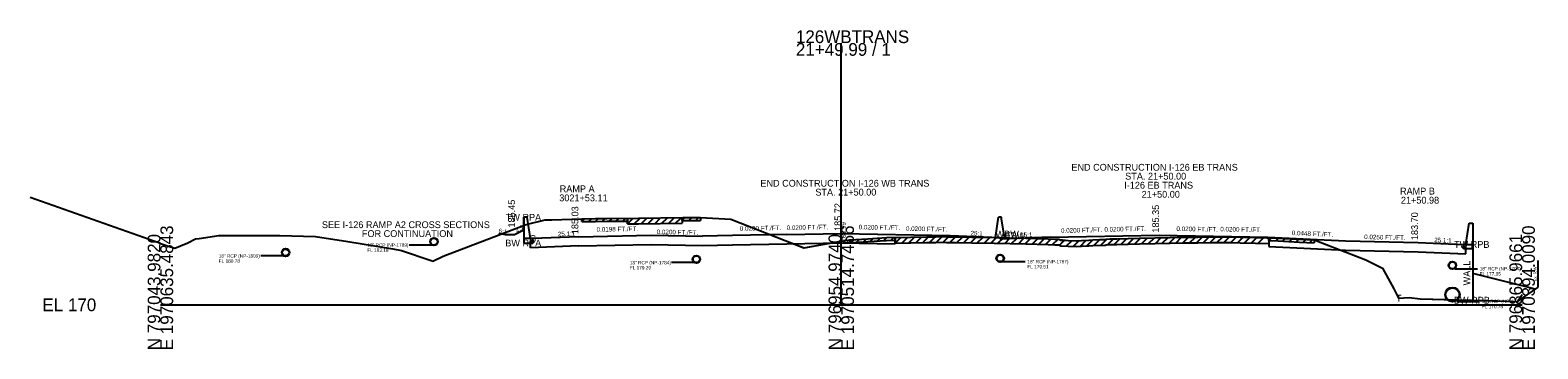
# Model space of a CAD drawing. Extents: x -6494 to 1970605, y -10 to 798140.
# Drawn here: x 971.3 to 1303.5, y 3990.3 to 4060.5 of the extents above; entities that cross this region are included whole.
import ezdxf

# ---------------------------------------------------------------- set-up
doc = ezdxf.new("R2010")
doc.units = 0
for name, color, linetype in [('RD_EX_SU_Misc_TxCode', 7, 'Continuous'), ('RD_GPK_XS_Cell', 7, 'Continuous'), ('RD_Sketch1', 7, 'Continuous'), ('RD_XS_Base', 7, 'Continuous'), ('RD_XS_Box', 7, 'Continuous'), ('RD_XS_EwShp', 7, 'Continuous'), ('RD_XS_ExGround', 7, 'Continuous'), ('RD_XS_ExPaveRet', 7, 'Continuous'), ('RD_XS_ExRW', 7, 'Continuous'), ('RD_XS_MedBWall', 7, 'Continuous'), ('RD_XS_Misc_Line', 7, 'Continuous'), ('RD_XS_Pave', 7, 'Continuous'), ('RD_XS_PaveOvlay', 7, 'Continuous'), ('RD_XS_PaveShd', 7, 'Continuous'), ('RD_XS_Pipe', 7, 'Continuous'), ('RD_XS_TieSlope', 7, 'Continuous'), ('RD_XS_TX_Elev_EX', 7, 'Continuous'), ('RD_XS_TX_Elev_PR', 7, 'Continuous'), ('RD_XS_TX_Misc', 7, 'Continuous'), ('RD_XS_TX_MkPT', 7, 'Continuous'), ('RD_XS_TX_Notes', 7, 'Continuous'), ('RD_XS_TX_Profile', 7, 'Continuous'), ('RD_XS_TX_Slope', 7, 'Continuous'), ('RD_XS_TX_Station', 7, 'Continuous')]:
    doc.layers.add(name, color=color, linetype=linetype)

msp = doc.modelspace()

# ---------------------------------------------------------------- linework, layer by layer
at = {"layer": 'RD_GPK_XS_Cell'}
for p, q in [((1150, 4000), (1150, 4057.66)), ((1000, 4000), (1150, 4000)), ((1150, 4000), (1300, 4000))]:
    msp.add_line(p, q, dxfattribs=at)
at = {"layer": 'RD_XS_Base'}
for p, q in [((1081.54, 4014.03), (1082.04, 4014.05)), ((1081.54, 4012.55), (1081.54, 4014.03)), ((1092.08, 4012.97), (1081.54, 4012.55)), ((1082.04, 4014.05), (1082.04, 4014.61)), ((1092.08, 4012.97), (1108.14, 4013.29)), ((1108.14, 4013.29), (1119.42, 4013.06)), ((1119.42, 4013.06), (1126, 4013.2)), ((1126, 4013.2), (1138, 4013.44)), ((1138, 4013.44), (1150, 4013.68)), ((1150, 4013.68), (1161.86, 4013.44)), ((1244.19, 4012.82), (1261.06, 4012.06)), ((1287.1, 4012.74), (1287.1, 4013.3)), ((1287.6, 4012.72), (1287.1, 4012.74)), ((1287.6, 4011.24), (1287.6, 4012.72)), ((1261.06, 4012.06), (1277.06, 4011.66)), ((1277.06, 4011.66), (1287.6, 4011.24))]:
    msp.add_line(p, q, dxfattribs=at)
at = {"layer": 'RD_XS_Box'}
for p, q in [((1080.04, 4016.45), (1080.04, 4014.61)), ((1082.04, 4014.61), (1080.04, 4014.61)), ((1287.1, 4013.3), (1289.11, 4013.3)), ((1289.11, 4013.3), (1289.11, 4001.02))]:
    msp.add_line(p, q, dxfattribs=at)
at = {"layer": 'RD_XS_ExGround'}
msp.add_line((1000, 4013.53), (971.31, 4023.67), dxfattribs=at)
for points in [[(1000, 4013.53), (1001.76, 4012.91), (1003.16, 4012.47), (1006.03, 4013.65), (1007.76, 4014.52), (1008.57, 4014.63), (1012.9, 4015.24), (1020.05, 4015.27), (1024.1, 4015.31), (1026.3, 4015.25), (1034.14, 4015.07), (1041.27, 4013.92), (1051.23, 4012.34), (1053.12, 4011.99), (1059.63, 4009.77), (1060.03, 4009.62), (1062.28, 4010.74), (1080.6, 4017.7), (1084.75, 4018.69), (1086.24, 4018.73), (1092.82, 4018.95), (1095.89, 4018.99), (1098.35, 4019.02), (1105.35, 4019.08), (1115.08, 4019.21), (1117.01, 4019.22), (1118.95, 4019.22), (1125.67, 4018.86), (1137.63, 4014.17), (1141.8, 4012.55), (1150, 4013.99), (1151.86, 4014.32), (1155.84, 4014.54), (1159.94, 4014.8), (1165.3, 4014.9), (1168.78, 4014.95), (1170.85, 4015), (1172.09, 4015.02), (1173.19, 4015), (1175.2, 4014.96), (1178.78, 4014.9), (1183.7, 4014.83), (1190.67, 4014.67), (1195.58, 4014.57), (1197.02, 4014.5), (1198.14, 4014.36), (1199.99, 4014.17), (1201.82, 4014.08), (1202.92, 4014.14), (1204.53, 4014.28), (1205.4, 4014.31), (1208.37, 4014.47), (1209.24, 4014.51), (1210.72, 4014.57), (1215.72, 4014.69), (1222.44, 4014.84), (1225.48, 4014.89), (1228.54, 4014.93), (1231.87, 4014.96), (1234.04, 4015), (1235.76, 4014.95), (1237.87, 4014.91), (1241.27, 4014.83), (1246.22, 4014.72), (1250.95, 4014.46), (1254.19, 4014.29), (1265.55, 4009.89), (1269.26, 4008.08), (1271.73, 4003.5), (1272.77, 4001.46), (1275.09, 4001.59), (1277.53, 4001.32), (1293.37, 4000.91), (1294.52, 4000.88), (1299, 4000.72), (1300, 4002.27)], [(1000, 4013.53), (1001.76, 4012.91), (1003.16, 4012.47), (1006.03, 4013.65), (1007.76, 4014.52), (1008.57, 4014.63), (1012.9, 4015.24), (1020.05, 4015.27), (1024.1, 4015.31), (1026.3, 4015.25), (1034.14, 4015.07), (1041.27, 4013.92), (1051.23, 4012.34), (1053.12, 4011.99), (1059.63, 4009.77), (1060.03, 4009.62), (1062.28, 4010.74), (1080.6, 4017.7), (1084.75, 4018.69), (1086.24, 4018.73), (1092.82, 4018.95), (1095.89, 4018.99), (1098.35, 4019.02), (1105.35, 4019.08), (1115.08, 4019.21), (1117.01, 4019.22), (1118.95, 4019.22), (1125.64, 4018.88), (1137.63, 4014.17), (1141.76, 4012.54), (1150, 4013.99), (1151.86, 4014.32), (1155.84, 4014.54), (1159.94, 4014.8), (1165.3, 4014.9), (1168.78, 4014.95), (1170.85, 4015), (1172.09, 4015.02), (1173.19, 4015), (1175.2, 4014.96), (1178.78, 4014.9), (1183.7, 4014.83), (1190.67, 4014.67), (1195.58, 4014.57), (1197.02, 4014.5), (1197.94, 4014.44), (1198.37, 4014.26), (1199.99, 4014.17), (1201.82, 4014.08), (1202.92, 4014.14), (1204.53, 4014.28), (1205.4, 4014.31), (1208.12, 4014.37), (1208.37, 4014.47), (1209.24, 4014.51), (1210.72, 4014.57), (1215.72, 4014.69), (1222.44, 4014.84), (1225.48, 4014.89), (1228.54, 4014.93), (1231.87, 4014.96), (1234.04, 4015), (1235.76, 4014.95), (1237.87, 4014.91), (1241.27, 4014.83), (1246.22, 4014.72), (1250.95, 4014.46), (1254.19, 4014.29), (1265.55, 4009.89), (1269.26, 4008.08), (1271.73, 4003.5), (1272.77, 4001.46), (1275.09, 4001.59), (1277.53, 4001.32), (1277.53, 4001.32), (1294.52, 4000.88), (1299, 4000.72), (1300, 4002.27)], [(1299, 4000.72), (1303.46, 4003.79)]]:
    msp.add_lwpolyline(points, dxfattribs=at)
at = {"layer": 'RD_XS_ExPaveRet'}
for p, q in [((1102.88, 4017.81), (1102.88, 4019.06)), ((1102.88, 4019.06), (1102.88, 4018.44)), ((1114.93, 4019.21), (1114.93, 4017.96)), ((1114.93, 4018.58), (1114.93, 4019.21)), ((1118.95, 4019.22), (1118.95, 4018.59)), ((1092.82, 4018.33), (1092.82, 4018.95)), ((1092.82, 4018.33), (1095.89, 4018.36)), ((1095.89, 4018.36), (1098.35, 4018.4)), ((1098.35, 4018.4), (1102.88, 4018.44)), ((1102.88, 4017.81), (1105.35, 4017.83)), ((1105.35, 4017.83), (1114.93, 4017.96)), ((1114.93, 4018.58), (1115.08, 4018.58)), ((1115.08, 4018.58), (1117.01, 4018.6)), ((1117.01, 4018.6), (1118.95, 4018.59)), ((1151.86, 4013.69), (1151.86, 4014.32)), ((1151.86, 4013.69), (1155.84, 4013.92)), ((1155.84, 4013.92), (1159.94, 4014.18)), ((1159.94, 4014.18), (1161.86, 4014.21)), ((1161.86, 4013.59), (1161.86, 4014.84)), ((1161.86, 4014.84), (1161.86, 4014.21)), ((1161.86, 4013.59), (1165.3, 4013.65)), ((1165.3, 4013.65), (1168.78, 4013.7)), ((1168.78, 4013.7), (1170.85, 4013.75)), ((1170.85, 4013.75), (1172.09, 4013.77)), ((1172.09, 4013.77), (1173.19, 4013.75)), ((1173.19, 4013.75), (1175.2, 4013.71)), ((1175.2, 4013.71), (1178.78, 4013.65)), ((1178.78, 4013.65), (1183.7, 4013.58)), ((1183.7, 4013.58), (1190.67, 4013.42)), ((1190.67, 4013.42), (1195.58, 4013.32)), ((1195.58, 4013.32), (1197.02, 4013.25)), ((1197.02, 4013.25), (1197.94, 4013.19)), ((1197.94, 4013.19), (1198.37, 4013.01)), ((1198.37, 4013.01), (1199.99, 4012.92)), ((1199.99, 4012.92), (1201.82, 4012.83)), ((1201.82, 4012.83), (1202.92, 4012.89)), ((1202.92, 4012.89), (1204.53, 4013.03)), ((1204.53, 4013.03), (1205.4, 4013.06)), ((1205.4, 4013.06), (1208.12, 4013.12)), ((1208.12, 4013.12), (1208.37, 4013.22)), ((1208.37, 4013.22), (1209.24, 4013.26)), ((1209.24, 4013.26), (1210.72, 4013.32)), ((1210.72, 4013.32), (1215.72, 4013.44)), ((1215.72, 4013.44), (1222.44, 4013.59)), ((1222.44, 4013.59), (1225.48, 4013.64)), ((1225.48, 4013.64), (1228.54, 4013.68)), ((1228.54, 4013.68), (1231.87, 4013.71)), ((1231.87, 4013.71), (1234.04, 4013.75)), ((1234.04, 4013.75), (1235.76, 4013.7)), ((1235.76, 4013.7), (1237.87, 4013.66)), ((1237.87, 4013.66), (1241.27, 4013.58)), ((1241.27, 4013.58), (1244.19, 4013.51)), ((1244.19, 4014.76), (1244.19, 4013.51)), ((1244.19, 4014.14), (1244.19, 4014.76)), ((1244.19, 4014.14), (1246.22, 4014.09)), ((1246.22, 4014.09), (1250.95, 4013.83)), ((1250.95, 4013.83), (1254.19, 4013.67)), ((1254.19, 4014.29), (1254.19, 4013.67))]:
    msp.add_line(p, q, dxfattribs=at)
at = {"layer": 'RD_XS_ExRW'}
msp.add_line((1303.46, 4009.79), (1303.46, 4003.79), dxfattribs=at)
at = {"layer": 'RD_XS_MedBWall'}
for p, q in [((1080.04, 4016.45), (1080.04, 4019.28)), ((1080.79, 4019.28), (1080.04, 4019.28)), ((1080.04, 4019.28), (1080.04, 4013.61)), ((1081.54, 4014.61), (1080.79, 4019.28)), ((1184, 4014.82), (1184.67, 4019.3)), ((1185.33, 4019.3), (1184.67, 4019.3)), ((1185.33, 4018.93), (1185.33, 4019.3)), ((1186, 4014.45), (1185.33, 4018.93)), ((1287.6, 4013.3), (1288.35, 4017.97)), ((1288.35, 4017.97), (1289.1, 4017.97)), ((1289.1, 4017.97), (1289.1, 4012.3)), ((1080.04, 4013.61), (1082.04, 4013.61)), ((1082.04, 4014.61), (1081.54, 4014.61)), ((1082.04, 4013.61), (1082.04, 4014.61)), ((1287.1, 4012.3), (1287.1, 4013.3)), ((1287.1, 4013.3), (1287.6, 4013.3)), ((1289.1, 4012.3), (1287.1, 4012.3))]:
    msp.add_line(p, q, dxfattribs=at)
at = {"layer": 'RD_XS_Misc_Line'}
for p, q in [((1101.87, 4018.43), (1102.51, 4019.06)), ((1102.88, 4017.81), (1104.15, 4019.07)), ((1104.39, 4017.83), (1105.66, 4019.09)), ((1105.89, 4017.84), (1107.17, 4019.11)), ((1107.4, 4017.86), (1108.68, 4019.13)), ((1108.91, 4017.88), (1110.19, 4019.15)), ((1110.42, 4017.9), (1111.69, 4019.17)), ((1111.93, 4017.92), (1113.2, 4019.19)), ((1113.44, 4017.94), (1114.71, 4019.2)), ((1114.93, 4018.58), (1115.56, 4019.21)), ((1116.44, 4018.59), (1117.07, 4019.22)), ((1117.95, 4018.59), (1118.57, 4019.22)), ((1092.82, 4018.33), (1093.45, 4018.96)), ((1094.33, 4018.34), (1094.96, 4018.98)), ((1095.84, 4018.36), (1096.47, 4018.99)), ((1097.35, 4018.38), (1097.98, 4019.02)), ((1098.85, 4018.4), (1099.49, 4019.03)), ((1100.36, 4018.42), (1101, 4019.05)), ((1151.86, 4013.69), (1152.53, 4014.35)), ((1153.37, 4013.78), (1154.04, 4014.44)), ((1154.88, 4013.86), (1155.54, 4014.53)), ((1156.39, 4013.95), (1157.06, 4014.62)), ((1157.89, 4014.05), (1158.56, 4014.72)), ((1159.4, 4014.14), (1160.07, 4014.8)), ((1160.91, 4014.19), (1161.55, 4014.83)), ((1161.86, 4013.59), (1163.14, 4014.86)), ((1163.37, 4013.61), (1164.65, 4014.89)), ((1164.88, 4013.64), (1166.16, 4014.91)), ((1166.39, 4013.67), (1167.66, 4014.94)), ((1167.9, 4013.69), (1169.18, 4014.96)), ((1169.4, 4013.72), (1170.69, 4014.99)), ((1170.91, 4013.75), (1172.2, 4015.02)), ((1172.42, 4013.77), (1173.65, 4014.99)), ((1173.93, 4013.74), (1175.16, 4014.96)), ((1175.44, 4013.7), (1176.68, 4014.93)), ((1176.95, 4013.68), (1178.18, 4014.91)), ((1178.46, 4013.66), (1179.69, 4014.89)), ((1179.97, 4013.63), (1181.2, 4014.86)), ((1181.47, 4013.61), (1182.71, 4014.84)), ((1182.98, 4013.59), (1184.22, 4014.81)), ((1184.49, 4013.56), (1185.72, 4014.78)), ((1186, 4013.53), (1187.23, 4014.75)), ((1187.51, 4013.49), (1188.74, 4014.72)), ((1189.02, 4013.46), (1190.25, 4014.68)), ((1190.53, 4013.43), (1191.76, 4014.65)), ((1192.03, 4013.4), (1193.27, 4014.62)), ((1193.54, 4013.36), (1194.77, 4014.59)), ((1195.05, 4013.33), (1196.26, 4014.54)), ((1196.56, 4013.27), (1197.75, 4014.46)), ((1198.07, 4013.14), (1199.15, 4014.22)), ((1199.58, 4012.94), (1200.77, 4014.13)), ((1201.09, 4012.87), (1202.34, 4014.11)), ((1202.6, 4012.87), (1203.96, 4014.23)), ((1204.1, 4012.99), (1205.43, 4014.31)), ((1205.61, 4013.06), (1206.9, 4014.34)), ((1207.12, 4013.1), (1208.51, 4014.48)), ((1208.63, 4013.23), (1209.94, 4014.54)), ((1210.14, 4013.3), (1211.44, 4014.59)), ((1211.65, 4013.35), (1212.93, 4014.62)), ((1213.16, 4013.38), (1214.44, 4014.66)), ((1214.67, 4013.41), (1215.95, 4014.69)), ((1216.17, 4013.45), (1217.46, 4014.73)), ((1217.68, 4013.48), (1218.97, 4014.76)), ((1219.19, 4013.52), (1220.48, 4014.8)), ((1220.7, 4013.55), (1221.99, 4014.83)), ((1222.21, 4013.59), (1223.49, 4014.86)), ((1223.72, 4013.61), (1224.99, 4014.88)), ((1225.23, 4013.63), (1226.5, 4014.9)), ((1226.73, 4013.65), (1228.01, 4014.92)), ((1228.24, 4013.67), (1229.52, 4014.94)), ((1229.75, 4013.69), (1231.02, 4014.95)), ((1231.26, 4013.71), (1232.54, 4014.98)), ((1232.77, 4013.73), (1234.05, 4015)), ((1234.28, 4013.75), (1235.5, 4014.96)), ((1235.79, 4013.7), (1237.02, 4014.93)), ((1237.3, 4013.67), (1238.53, 4014.9)), ((1238.8, 4013.64), (1240.03, 4014.86)), ((1240.31, 4013.6), (1241.54, 4014.82)), ((1241.82, 4013.57), (1243.05, 4014.79)), ((1244.19, 4014.14), (1244.81, 4014.75)), ((1245.7, 4014.1), (1246.31, 4014.71)), ((1247.21, 4014.04), (1247.81, 4014.63)), ((1248.72, 4013.95), (1249.32, 4014.55)), ((1250.23, 4013.87), (1250.82, 4014.46)), ((1251.74, 4013.79), (1252.34, 4014.39)), ((1253.25, 4013.72), (1253.84, 4014.31))]:
    msp.add_line(p, q, dxfattribs=at)
at = {"layer": 'RD_XS_Pave'}
for p, q in [((1092.08, 4015.01), (1108.14, 4015.33)), ((1138, 4015.48), (1126, 4015.24)), ((1138, 4015.48), (1150, 4015.72)), ((1150, 4015.72), (1174, 4015.24)), ((1196, 4014.87), (1220, 4015.35)), ((1196, 4014.87), (1220, 4015.35)), ((1220, 4015.35), (1244, 4014.87)), ((1220, 4015.35), (1244, 4014.87)), ((1244, 4014.87), (1261.06, 4014.1)), ((1261.06, 4014.1), (1277.06, 4013.7))]:
    msp.add_line(p, q, dxfattribs=at)
at = {"layer": 'RD_XS_PaveOvlay'}
for p, q in [((1161.86, 4014.84), (1165.3, 4014.9)), ((1161.86, 4014.84), (1161.86, 4013.44)), ((1165.3, 4014.9), (1168.78, 4014.95)), ((1168.78, 4014.95), (1170.85, 4015)), ((1170.85, 4015), (1172.09, 4015.02)), ((1172.09, 4015.02), (1173.19, 4015)), ((1173.19, 4015), (1175.2, 4014.96)), ((1175.2, 4014.96), (1178.78, 4014.9)), ((1178.78, 4014.9), (1183.7, 4014.83)), ((1183.7, 4014.83), (1190.67, 4014.67)), ((1190.67, 4014.67), (1195.58, 4014.57)), ((1195.58, 4014.57), (1197.02, 4014.5)), ((1197.02, 4014.5), (1197.94, 4014.44)), ((1197.94, 4014.44), (1198.37, 4014.26)), ((1198.37, 4014.26), (1199.99, 4014.17)), ((1199.99, 4014.17), (1201.82, 4014.08)), ((1201.82, 4014.08), (1202.92, 4014.14)), ((1202.92, 4014.14), (1204.53, 4014.28)), ((1204.53, 4014.28), (1205.4, 4014.31)), ((1205.4, 4014.31), (1208.12, 4014.37)), ((1208.12, 4014.37), (1208.37, 4014.47)), ((1208.37, 4014.47), (1209.24, 4014.51)), ((1209.24, 4014.51), (1210.72, 4014.57)), ((1210.72, 4014.57), (1215.72, 4014.69)), ((1215.72, 4014.69), (1222.44, 4014.84)), ((1222.44, 4014.84), (1225.48, 4014.89)), ((1225.48, 4014.89), (1228.54, 4014.93)), ((1228.54, 4014.93), (1231.87, 4014.96)), ((1231.87, 4014.96), (1234.04, 4015)), ((1234.04, 4015), (1235.76, 4014.95)), ((1235.76, 4014.95), (1237.87, 4014.91)), ((1237.87, 4014.91), (1241.27, 4014.83)), ((1241.27, 4014.83), (1244.19, 4014.76)), ((1244.19, 4014.76), (1244.19, 4012.82))]:
    msp.add_line(p, q, dxfattribs=at)
at = {"layer": 'RD_XS_PaveShd'}
for p, q in [((1092.08, 4015.01), (1082.04, 4014.61)), ((1108.14, 4015.33), (1119.42, 4015.1)), ((1126, 4015.24), (1119.42, 4015.1)), ((1174, 4015.24), (1185, 4014.8)), ((1196, 4014.87), (1185, 4014.43)), ((1185, 4014.8), (1185, 4014.43)), ((1277.06, 4013.7), (1287.1, 4013.3))]:
    msp.add_line(p, q, dxfattribs=at)
at = {"layer": 'RD_XS_Pipe'}
for p, q in [((1059.77, 4013.18), (1054.77, 4013.18)), ((1027.09, 4010.78), (1022.09, 4010.78)), ((1117.59, 4009.29), (1112.59, 4009.29)), ((1185.5, 4009.51), (1190.5, 4009.51)), ((1285.14, 4007.95), (1290.14, 4007.95)), ((1285.64, 4000.75), (1290.64, 4000.75))]:
    msp.add_line(p, q, dxfattribs=at)
for centre, radius in [((1060.27, 4013.93), 0.85), ((1060.27, 4013.93), 0.75), ((1027.59, 4011.53), 0.85), ((1027.59, 4011.53), 0.75), ((1118.09, 4010.04), 0.85), ((1118.09, 4010.04), 0.75), ((1185, 4010.26), 0.85), ((1185, 4010.26), 0.75), ((1284.64, 4008.7), 0.85), ((1284.64, 4008.7), 0.75), ((1284.64, 4002.25), 1.6), ((1284.64, 4002.25), 1.5)]:
    msp.add_circle(centre, radius, dxfattribs=at)
at = {"layer": 'RD_XS_TieSlope'}
for p, q in [((1080.04, 4016.45), (1078.04, 4015.45)), ((1074.61, 4015.69), (1074.61, 4015.42)), ((1076.04, 4015.45), (1074.61, 4015.69)), ((1078.04, 4015.45), (1076.04, 4015.45)), ((1302.93, 4003.42), (1289.11, 4006.87))]:
    msp.add_line(p, q, dxfattribs=at)

# ---------------------------------------------------------------- texts
at = {"layer": 'RD_EX_SU_Misc_TxCode'}
msp.add_text('G', height=1.5, dxfattribs=at).set_placement((1081.29, 4013.86))
at = {"layer": 'RD_GPK_XS_Cell'}
for s, p in [('126WBTRANS', (1140, 4057.66)), ('21+49.99 / 1', (1140, 4054.86)), ('EL 170', (974, 3998.6))]:
    msp.add_text(s, height=2.8, dxfattribs=at).set_placement(p)
for s, p in [('E 1970635.4843', (1002.8, 3990)), ('E 1970514.7466', (1152.8, 3990)), ('E 1970394.0090', (1302.8, 3990)), ('N 797043.9820', (1000, 3990)), ('N 796954.9740', (1150, 3990)), ('N 796865.9661', (1300, 3990))]:
    msp.add_text(s, height=2.8, rotation=90, dxfattribs=at).set_placement(p)
at = {"layer": 'RD_Sketch1'}
msp.add_text('T', height=1.5, dxfattribs=at).set_placement((1272.21, 4000.71))
at = {"layer": 'RD_XS_EwShp'}
for s, p in [('TW RPA', (1076.08, 4018.53)), ('BW RPA', (1075.98, 4012.86)), ('TW RPB', (1285, 4012.55)), ('BW RPB', (1284.97, 4000.27))]:
    msp.add_text(s, height=1.5, dxfattribs=at).set_placement(p)
at = {"layer": 'RD_XS_ExRW'}
msp.add_text('Ex. R/W ', height=0.65, rotation=90, dxfattribs=at).set_placement((1303.21, 4005.17))
at = {"layer": 'RD_XS_Pipe'}
for s, p in [('18" RCP (NP-1789)', (1045.59, 4012.8)), ('FL 183.18', (1045.59, 4011.68)), ('18" RCP (NP-1809)', (1012.86, 4010.4)), ('FL 180.78', (1012.86, 4009.28)), ('18" RCP (NP-1784)', (1103.42, 4008.92)), ('18" RCP (NP-1787)', (1191, 4009.14)), ('FL 179.29', (1103.42, 4007.79)), ('FL 179.51', (1191, 4008.01)), ('18" RCP (NP-1794)', (1290.64, 4007.57)), ('FL 177.95', (1290.64, 4006.45)), ('36" RCP (NP-1773)', (1291.14, 4000.38)), ('FL 170.75', (1291.14, 3999.25))]:
    msp.add_text(s, height=0.75, dxfattribs=at).set_placement(p)
at = {"layer": 'RD_XS_TX_Elev_EX'}
msp.add_text('183.99', height=1, rotation=90, dxfattribs=at).set_placement((1151, 4013.99))
at = {"layer": 'RD_XS_TX_Elev_PR'}
for s, p in [(' 185.03', (1092.08, 4015.01)), (' 185.72', (1150, 4015.72)), (' 185.35', (1220, 4015.35)), (' 183.70', (1277.06, 4013.7))]:
    msp.add_text(s, height=1.5, rotation=90, dxfattribs=at).set_placement(p)
at = {"layer": 'RD_XS_TX_Misc'}
msp.add_text('185.45', height=1.5, rotation=90, dxfattribs=at).set_placement((1078.12, 4017.02))
at = {"layer": 'RD_XS_TX_MkPT'}
for s, p in [('WBW', (1184, 4014.82)), ('EBW', (1186, 4014.45))]:
    msp.add_text(s, height=1.5, dxfattribs=at).set_placement(p)
at = {"layer": 'RD_XS_TX_Notes'}
for s, p in [('END CONSTRUCTION I-126 EB TRANS', (1200.69, 4029.55)), ('STA. 21+50.00', (1212.55, 4027.59)), ('END CONSTRUCTION I-126 WB TRANS', (1132.18, 4026.03)), ('STA. 21+50.00', (1144.29, 4024.07)), ('SEE I-126 RAMP A2 CROSS SECTIONS', (1035.58, 4016.9)), ('FOR CONTINUATION', (1044.39, 4014.94))]:
    msp.add_text(s, height=1.5, dxfattribs=at).set_placement(p)
msp.add_text('WALL', height=1.5, rotation=90, dxfattribs=at).set_placement((1288.55, 4004.29))
at = {"layer": 'RD_XS_TX_Profile'}
for s, rotation, p in [('25:1', 357.7094, (1178.46, 4015.31)), ('25:1', 2.2906, (1189.44, 4014.86)), ('25.1:1', 357.7181, (1280.61, 4013.81))]:
    msp.add_text(s, height=1, rotation=rotation, dxfattribs=at).set_placement(p)
at = {"layer": 'RD_XS_TX_Slope'}
for s, rotation, p in [('6:1', 350.5377, (1074.42, 4015.86)), ('2:1', 26.5651, (1078.44, 4015.96)), ('25.1:1', 2.2825, (1087.58, 4015.08)), ('0.0198 FT./FT.', 1.1347, (1096.1, 4016.09)), ('0.0200 FT./FT.', 358.8542, (1109.32, 4015.6)), ('0.0200 FT./FT.', 1.1458, (1127.65, 4016.29)), ('0.0200 FT./FT.', 1.1458, (1137.98, 4016.48)), ('0.0200 FT./FT.', 358.8542, (1153.83, 4016.64)), ('0.0200 FT./FT.', 358.8542, (1164.24, 4016.32)), ('0.0200 FT./FT.', 1.1458, (1198.41, 4015.86)), ('0.0200 FT./FT.', 1.1458, (1207.98, 4016.11)), ('0.0200 FT./FT.', 358.8542, (1223.83, 4016.28)), ('0.0200 FT./FT.', 358.8542, (1233.49, 4016.19)), ('0.0448 FT./FT.', 357.4376, (1249.23, 4015.37)), ('0.0250 FT./FT.', 358.5676, (1265.19, 4014.49))]:
    msp.add_text(s, height=1, rotation=rotation, dxfattribs=at).set_placement(p)
at = {"layer": 'RD_XS_TX_Station'}
for s, p in [('RAMP A', (1087.97, 4024.81)), ('I-126 EB TRANS', (1212.34, 4025.6)), ('RAMP B', (1273.09, 4024.3)), ('3021+53.11', (1087.87, 4022.81)), ('21+50.00', (1216.17, 4023.6)), ('21+50.98', (1273.29, 4022.3))]:
    msp.add_text(s, height=1.5, dxfattribs=at).set_placement(p)

doc.saveas('drawing.dxf')
